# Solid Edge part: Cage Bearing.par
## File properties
Title: Roller Bearing Cage
Author: Dan
Comments: R1-30 ENRIGHT
Template: Normal.par
Last saved by: Dan
Revision: 28
Application: Solid Edge
Material: ptfe nylon
Density: 0 kg/mm^3
Accuracy: 0.99
Document Number: P52-004-2
Project Name: Piston Pump P52
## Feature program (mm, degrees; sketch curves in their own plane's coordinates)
sketch for "unnamed Protrusion 1" #1 plane through (8.9826, -19.0478, 0) normal (0, 0, 1) x-axis (1, 0, 0)
sketch for "unnamed Protrusion 1" #2 plane through (8.9826, -19.0478, 0) normal (0, 0, 1) x-axis (1, 0, 0)
  circle centre (-8.9826, 19.0478) radius 23
extrude "unnamed Protrusion 1" add finite 10.8 along -normal
sketch for "ExtrudedCutout_82" plane through (0, 0, -10.8) normal (0, 0, -1) x-axis (1, 0, 0)
extrude "ExtrudedCutout_82" cut finite 8.3 along -normal
pattern "unnamed Pattern 1" of "ExtrudedCutout_82"
extrude "unnamed Cutout 1" cut finite 8.3
extrude "unnamed Cutout 2" cut finite 8.3
extrude "unnamed Cutout 3" cut finite 8.3
extrude "unnamed Cutout 4" cut finite 8.3
extrude "unnamed Cutout 5" cut finite 8.3
extrude "unnamed Cutout 6" cut finite 8.3
extrude "unnamed Cutout 7" cut finite 8.3
extrude "unnamed Cutout 8" cut finite 8.3
extrude "unnamed Cutout 9" cut finite 8.3
extrude "unnamed Cutout 10" cut finite 8.3
extrude "unnamed Cutout 11" cut finite 8.3
extrude "unnamed Cutout 12" cut finite 8.3
extrude "unnamed Cutout 13" cut finite 8.3
extrude "unnamed Cutout 14" cut finite 8.3
extrude "unnamed Cutout 15" cut finite 8.3
extrude "unnamed Cutout 16" cut finite 8.3
extrude "unnamed Cutout 17" cut finite 8.3
extrude "unnamed Cutout 18" cut finite 8.3
extrude "unnamed Cutout 19" cut finite 8.3
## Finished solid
Body 1: solid body, 83 faces, 242 edges, 160 vertices.
  Faces by surface: cylinder 42, plane 41
  Edges by curve: circle 162, line 80
Bounding box of the edges (mm): 53.001 x 53.001 x 10.800, from (-26.5005, -26.5005, -10.8) to (26.5005, 26.5005, 0).
Cylindrical faces by radius (mm): R2.65 x40, R23 x1, R26.5005 x1
Planar faces by outward normal: +z 1, -z 40
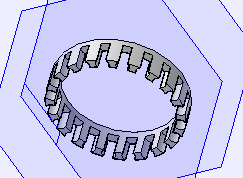
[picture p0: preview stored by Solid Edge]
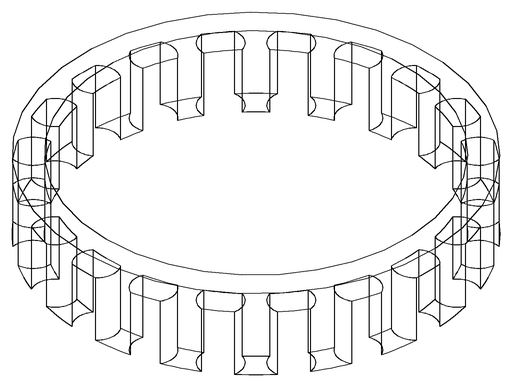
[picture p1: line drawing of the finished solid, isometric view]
